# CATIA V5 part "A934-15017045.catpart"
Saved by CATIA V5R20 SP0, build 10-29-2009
Part number: A934-15017045
Source: Unknown
Property "A": "110.000"
Property "ARTICLENO": "A934-15017045"
Property "B": "20.000"
Property "BOMINFO": "A934-15017045"
Property "CODE": "A934-15017045"
Property "L": "170.000"
Property "L1": "143.370"
Property "LINA": "A934-15017045"
Property "NB": "A934-15017045"
Property "NBSYN": "$CODE."
Property "NN": "A934"
Property "NT": "VDI 3357 H-Type Cam Drivers, self-lubricating"
Property "SUPPLIER": "CF"
Property "T": "45.000"
Property "W": "150.000"
Bounding box of the stored display mesh (mm): x 0 to 170, y 0 to 45, z -150 to 0
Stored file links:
  C:\Users\Utente\Desktop\3D files A934\A934-15017045.catpart
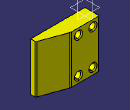
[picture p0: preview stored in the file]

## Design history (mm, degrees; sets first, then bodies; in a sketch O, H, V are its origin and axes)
Body1 "Geometry.1" (main body)
  Solid1 "A934-15017045.catpart": solid without history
